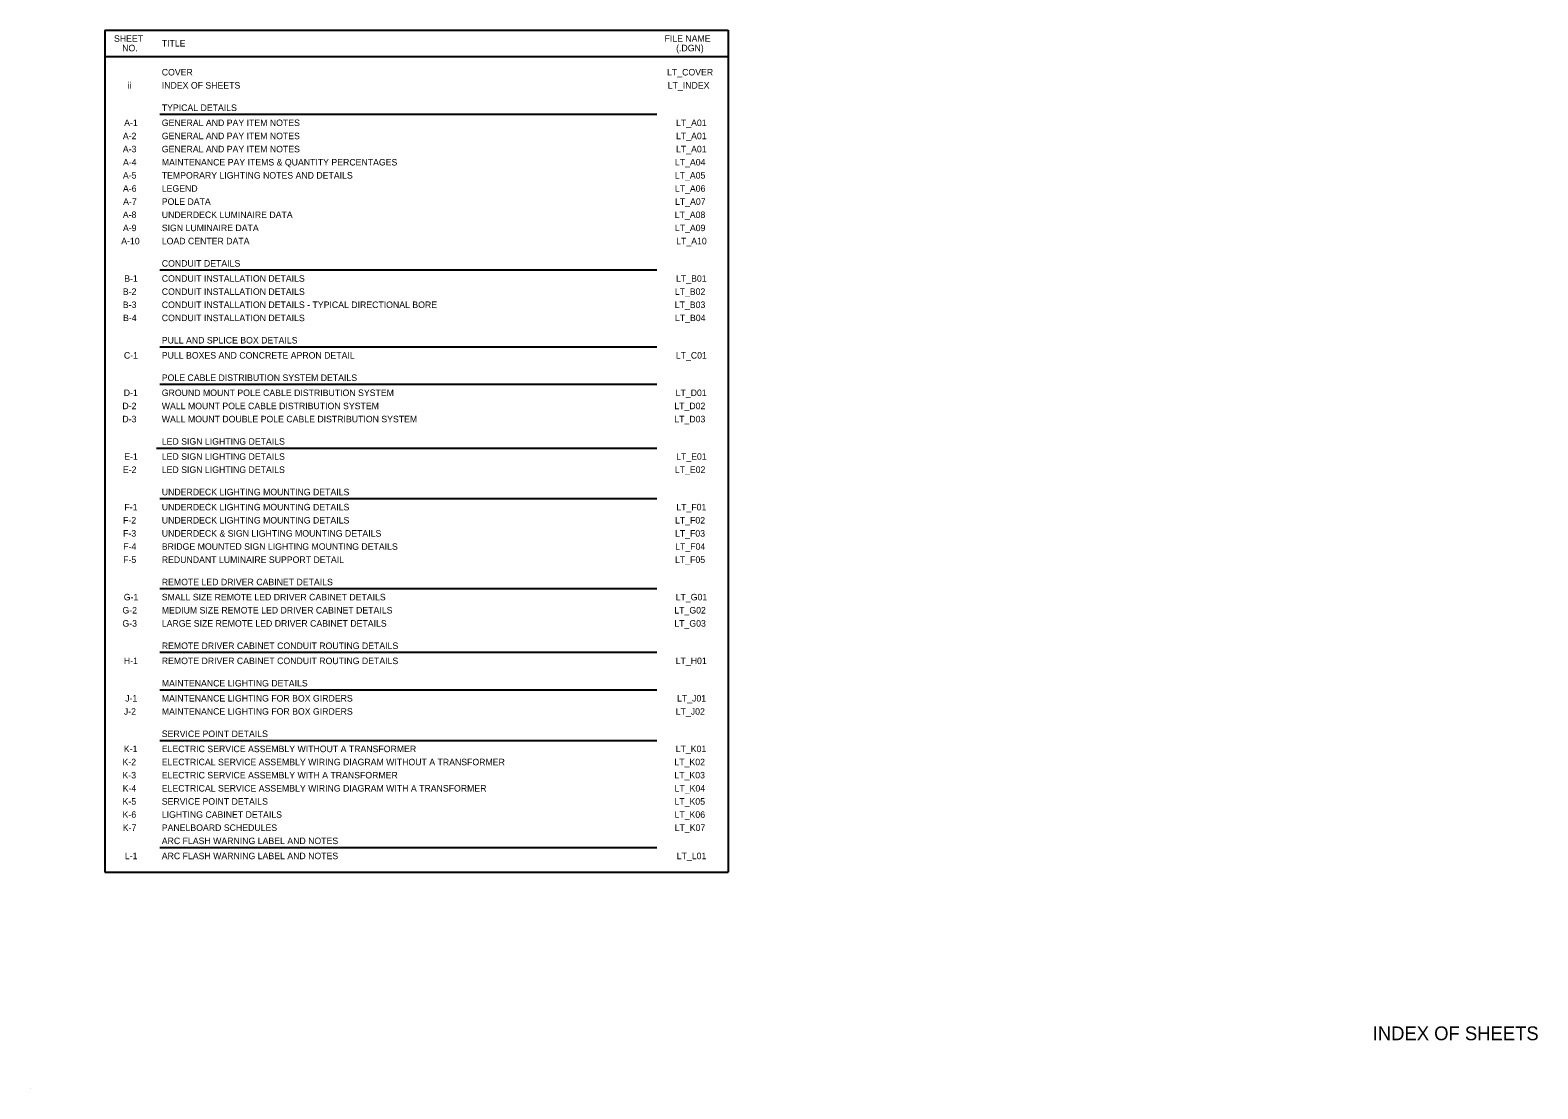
# Model space of a CAD drawing. Extents: x -39 to 1294, y -523 to -44.
# Drawn here: x -39 to 644, y -523 to -44 of the extents above; entities that cross this region are included whole.
import ezdxf

# ---------------------------------------------------------------- set-up
doc = ezdxf.new("R2010")
doc.units = 0
for name, color, linetype in [('AdhocPoint_dp', 7, 'Continuous'), ('SumBoxLines_dp', 7, 'Continuous'), ('SumBoxLinesMin_dp', 7, 'Continuous'), ('TextLabel', 7, 'Continuous'), ('TextMisc', 7, 'Continuous')]:
    doc.layers.add(name, color=color, linetype=linetype)

msp = doc.modelspace()

# ---------------------------------------------------------------- linework, layer by layer
at = {"layer": 'AdhocPoint_dp'}
msp.add_line((-39.15, -523.47), (-39.15, -523.47), dxfattribs=at)
at = {"layer": 'SumBoxLines_dp'}
for p, q in [((-5.35, -55.48), (18.08, -55.48)), ((-5.35, -55.48), (277.18, -55.48)), ((19.67, -55.48), (277.18, -55.48)), ((19.67, -81.7), (244.87, -81.7)), ((19.67, -81.7), (244.87, -81.7)), ((19.67, -152.27), (244.87, -152.27)), ((19.67, -152.27), (244.87, -152.27)), ((19.67, -187.11), (244.87, -187.11)), ((19.67, -187.11), (244.87, -187.11)), ((19.67, -204.09), (244.87, -204.09)), ((19.67, -204.09), (244.87, -204.09)), ((18.08, -232.98), (244.87, -232.98)), ((18.08, -232.98), (244.87, -232.98)), ((19.67, -255.91), (244.87, -255.91)), ((19.67, -255.91), (244.87, -255.91)), ((19.67, -296.71), (244.87, -296.71)), ((19.67, -296.71), (244.87, -296.71)), ((19.67, -325.59), (244.87, -325.59)), ((19.67, -325.59), (244.87, -325.59)), ((19.67, -342.57), (244.87, -342.57)), ((19.67, -342.57), (244.87, -342.57)), ((19.67, -365.5), (244.87, -365.5)), ((19.67, -365.5), (244.87, -365.5)), ((19.67, -414.03), (244.87, -414.03)), ((19.67, -414.03), (244.87, -414.03))]:
    msp.add_line(p, q, dxfattribs=at)
at = {"layer": 'SumBoxLinesMin_dp'}
for p, q in [((-5.35, -43.57), (277.18, -43.57)), ((-5.35, -43.57), (-5.35, -425.18)), ((277.18, -43.57), (277.18, -425.18)), ((-5.35, -425.18), (277.18, -425.18))]:
    msp.add_line(p, q, dxfattribs=at)

# ---------------------------------------------------------------- texts
at = {"layer": 'TextLabel'}
for s, height, p in [('SHEET', 2.956, (-1.15, -48.85)), ('FILE NAME', 2.956, (248.38, -48.85)), ('NO.', 2.956, (2.56, -53.15)), ('TITLE', 2.956, (20.51, -51)), ('(.DGN)', 2.956, (253.63, -53.15)), ('COVER', 2.956, (20.51, -64.11)), ('LT_COVER', 2.956, (249.55, -64.11)), ('ii', 2.956, (5.07, -70.07)), ('INDEX OF SHEETS', 2.9563, (20.51, -70.07)), ('LT_INDEX', 2.956, (249.85, -70.07)), ('TYPICAL DETAILS', 2.9563, (20.51, -80.2)), ('A-1', 2.956, (3.46, -87.04)), ('GENERAL AND PAY ITEM NOTES', 2.9563, (20.51, -87.04)), ('LT_A01', 2.956, (253.61, -87.04)), ('A-2', 2.956, (2.86, -93)), ('GENERAL AND PAY ITEM NOTES', 2.9563, (20.51, -93)), ('LT_A01', 2.956, (253.61, -93)), ('A-3', 2.956, (2.86, -98.95)), ('A-4', 2.956, (2.93, -104.91)), ('GENERAL AND PAY ITEM NOTES', 2.9563, (20.51, -98.95)), ('MAINTENANCE PAY ITEMS & QUANTITY PERCENTAGES', 2.9563, (20.51, -104.91)), ('LT_A04', 2.956, (253.08, -104.91)), ('LT_A01', 2.956, (253.61, -98.95)), ('A-5', 2.956, (2.89, -110.86)), ('TEMPORARY LIGHTING NOTES AND DETAILS', 2.9563, (20.51, -110.86)), ('LT_A05', 2.956, (253.04, -110.86)), ('A-6', 2.956, (2.91, -116.82)), ('LEGEND', 2.956, (20.51, -116.82)), ('LT_A06', 2.956, (253.06, -116.82)), ('A-7', 2.956, (2.99, -122.77)), ('POLE DATA', 2.956, (20.51, -122.77)), ('LT_A07', 2.956, (253.14, -122.77)), ('A-8', 2.956, (2.86, -128.73)), ('UNDERDECK LUMINAIRE DATA', 2.9563, (20.51, -128.73)), ('LT_A08', 2.956, (253.01, -128.73)), ('A-9', 2.956, (2.91, -134.68)), ('SIGN LUMINAIRE DATA', 2.9563, (20.51, -134.68)), ('LT_A09', 2.956, (253.06, -134.68)), ('A-10', 2.956, (2.13, -140.64)), ('LOAD CENTER DATA', 2.9563, (20.51, -140.64)), ('LT_A10', 2.956, (253.65, -140.64)), ('CONDUIT DETAILS', 2.9563, (20.51, -150.77)), ('B-1', 2.956, (3.48, -157.61)), ('CONDUIT INSTALLATION DETAILS', 2.9563, (20.51, -157.61)), ('LT_B01', 2.956, (253.63, -157.61)), ('B-2', 2.956, (2.88, -163.57)), ('CONDUIT INSTALLATION DETAILS', 2.9563, (20.51, -163.57)), ('LT_B02', 2.956, (253.03, -163.57)), ('B-3', 2.956, (2.87, -169.52)), ('CONDUIT INSTALLATION DETAILS - TYPICAL DIRECTIONAL BORE', 2.9563, (20.51, -169.52)), ('LT_B03', 2.956, (253.02, -169.52)), ('B-4', 2.956, (2.95, -175.48)), ('CONDUIT INSTALLATION DETAILS', 2.9563, (20.51, -175.48)), ('LT_B04', 2.956, (253.1, -175.48)), ('PULL AND SPLICE BOX DETAILS', 2.9563, (20.51, -185.61)), ('C-1', 2.956, (3.34, -192.46)), ('PULL BOXES AND CONCRETE APRON DETAIL', 2.9563, (20.51, -192.46)), ('LT_C01', 2.956, (253.49, -192.46)), ('POLE CABLE DISTRIBUTION SYSTEM DETAILS', 2.9563, (20.51, -202.59)), ('D-1', 2.956, (3.26, -209.43)), ('GROUND MOUNT POLE CABLE DISTRIBUTION SYSTEM', 2.9563, (20.51, -209.43)), ('LT_D01', 2.956, (253.41, -209.43)), ('D-2', 2.956, (2.66, -215.39)), ('D-3', 2.956, (2.65, -221.34)), ('WALL MOUNT POLE CABLE DISTRIBUTION SYSTEM', 2.9563, (20.51, -215.39)), ('WALL MOUNT DOUBLE POLE CABLE DISTRIBUTION SYSTEM', 2.9563, (20.51, -221.34)), ('LT_D02', 2.956, (252.81, -215.39)), ('LT_D03', 2.956, (252.8, -221.34)), ('LED SIGN LIGHTING DETAILS', 2.9563, (20.51, -231.48)), ('E-1', 2.956, (3.49, -238.32)), ('LED SIGN LIGHTING DETAILS', 2.9563, (20.51, -238.32)), ('LT_E01', 2.956, (253.64, -238.32)), ('E-2', 2.956, (2.89, -244.28)), ('LED SIGN LIGHTING DETAILS', 2.9563, (20.51, -244.28)), ('LT_E02', 2.956, (253.04, -244.28)), ('UNDERDECK LIGHTING MOUNTING DETAILS', 2.9563, (20.51, -254.41)), ('F-1', 2.956, (3.57, -261.25)), ('UNDERDECK LIGHTING MOUNTING DETAILS', 2.9563, (20.51, -261.25)), ('LT_F01', 2.956, (253.72, -261.25)), ('F-2', 2.956, (2.98, -267.21)), ('UNDERDECK LIGHTING MOUNTING DETAILS', 2.9563, (20.51, -267.21)), ('LT_F02', 2.956, (253.13, -267.21)), ('F-3', 2.956, (2.97, -273.16)), ('UNDERDECK & SIGN LIGHTING MOUNTING DETAILS', 2.9563, (20.51, -273.16)), ('LT_F03', 2.956, (253.12, -273.16)), ('F-4', 2.956, (3.05, -279.12)), ('BRIDGE MOUNTED SIGN LIGHTING MOUNTING DETAILS', 2.9563, (20.51, -279.12)), ('LT_F04', 2.956, (253.2, -279.12)), ('F-5', 2.956, (3.01, -285.07)), ('REDUNDANT LUMINAIRE SUPPORT DETAIL', 2.9563, (20.51, -285.07)), ('LT_F05', 2.956, (253.16, -285.07)), ('REMOTE LED DRIVER CABINET DETAILS', 2.9563, (20.51, -295.21)), ('G-1', 2.956, (3.28, -302.05)), ('SMALL SIZE REMOTE LED DRIVER CABINET DETAILS', 2.9563, (20.51, -302.05)), ('LT_G01', 2.956, (253.43, -302.05)), ('G-2', 2.956, (2.68, -308)), ('MEDIUM SIZE REMOTE LED DRIVER CABINET DETAILS', 2.9563, (20.51, -308)), ('LT_G02', 2.956, (252.83, -308)), ('G-3', 2.956, (2.67, -313.96)), ('LARGE SIZE REMOTE LED DRIVER CABINET DETAILS', 2.9563, (20.51, -313.96)), ('LT_G03', 2.956, (252.82, -313.96)), ('REMOTE DRIVER CABINET CONDUIT ROUTING DETAILS', 2.9563, (20.51, -324.09)), ('H-1', 2.956, (3.3, -330.94)), ('REMOTE DRIVER CABINET CONDUIT ROUTING DETAILS', 2.9563, (20.51, -330.94)), ('LT_H01', 2.956, (253.45, -330.94)), ('MAINTENANCE LIGHTING DETAILS', 2.9563, (20.51, -341.07)), ('J-1', 2.956, (3.91, -347.91)), ('MAINTENANCE LIGHTING FOR BOX GIRDERS', 2.9563, (20.51, -347.91)), ('LT_J01', 2.956, (254.06, -347.91)), ('J-2', 2.956, (3.31, -353.87)), ('MAINTENANCE LIGHTING FOR BOX GIRDERS', 2.9563, (20.51, -353.87)), ('LT_J02', 2.956, (253.46, -353.87)), ('SERVICE POINT DETAILS', 2.9563, (20.51, -364)), ('K-1', 2.956, (3.31, -370.85)), ('ELECTRIC SERVICE ASSEMBLY WITHOUT A TRANSFORMER', 2.9563, (20.51, -370.85)), ('LT_K01', 2.956, (253.46, -370.85)), ('K-2', 2.956, (2.71, -376.8)), ('ELECTRICAL SERVICE ASSEMBLY WIRING DIAGRAM WITHOUT A TRANSFORMER', 2.9563, (20.51, -376.8)), ('LT_K02', 2.956, (252.86, -376.8)), ('K-3', 2.956, (2.7, -382.76)), ('ELECTRIC SERVICE ASSEMBLY WITH A TRANSFORMER', 2.9563, (20.51, -382.76)), ('LT_K03', 2.956, (252.85, -382.76)), ('K-4', 2.956, (2.78, -388.71)), ('ELECTRICAL SERVICE ASSEMBLY WIRING DIAGRAM WITH A TRANSFORMER', 2.9563, (20.51, -388.71)), ('LT_K04', 2.956, (252.93, -388.71)), ('K-5', 2.956, (2.74, -394.66)), ('SERVICE POINT DETAILS', 2.9563, (20.51, -394.66)), ('LT_K05', 2.956, (252.89, -394.66)), ('K-6', 2.956, (2.76, -400.62)), ('LIGHTING CABINET DETAILS', 2.9563, (20.51, -400.62)), ('LT_K06', 2.956, (252.91, -400.62)), ('K-7', 2.956, (2.84, -406.57)), ('ARC FLASH WARNING LABEL AND NOTES', 2.9563, (20.51, -412.53)), ('PANELBOARD SCHEDULES', 2.9563, (20.51, -406.57)), ('LT_K07', 2.956, (252.99, -406.57)), ('L-1', 2.956, (3.78, -419.37)), ('ARC FLASH WARNING LABEL AND NOTES', 2.9563, (20.51, -419.37)), ('LT_L01', 2.956, (253.93, -419.37))]:
    msp.add_text(s, height=height, dxfattribs=at).set_placement(p)
at = {"layer": 'TextMisc'}
msp.add_text('       INDEX OF SHEETS         ', height=6.25, dxfattribs=at).set_placement((553.1, -501.43))

doc.saveas('drawing.dxf')
